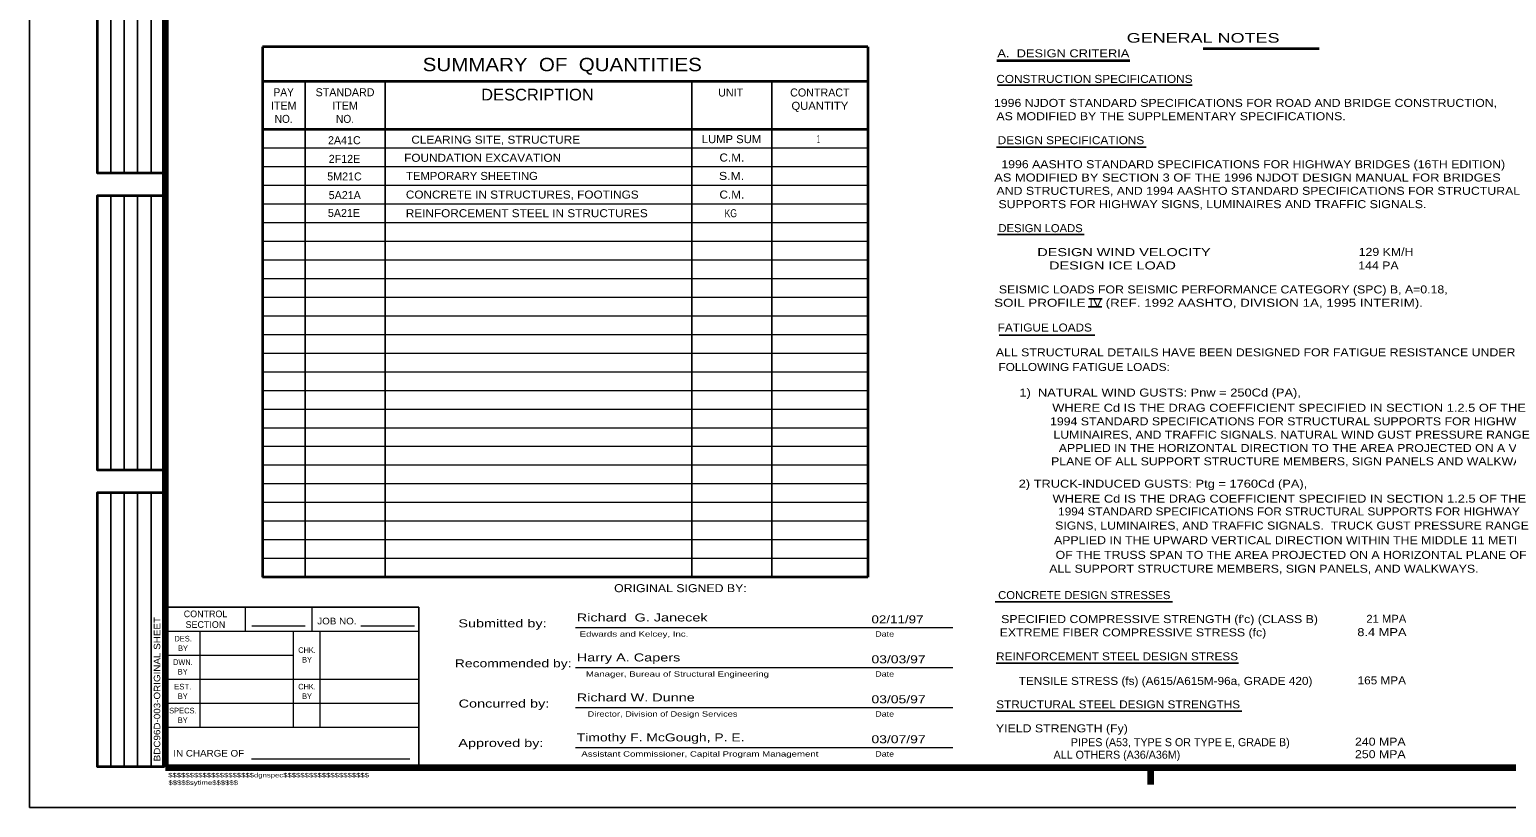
# Model space of a CAD drawing. Extents: x 312601.858 to 312602.699, y 144420.109 to 144420.704.
# Drawn here: x 312601.858 to 312602.412, y 144420.109 to 144420.401 of the extents above; entities that cross this region are included whole.
import ezdxf
from ezdxf.enums import TextEntityAlignment as Align

# ---------------------------------------------------------------- set-up
doc = ezdxf.new("R2010")
doc.units = 0
doc.header["$LTSCALE"] = 0.0012
for name, color, linetype, lineweight in [('1', 7, 'Continuous', 25), ('2', 7, 'Continuous', 13), ('39', 7, 'Continuous', 13), ('60', 7, 'Continuous', 25)]:
    doc.layers.add(name, color=color, linetype=linetype, lineweight=lineweight)
doc.layers.add('4', color=7, linetype='Continuous')

msp = doc.modelspace()

# ---------------------------------------------------------------- linework, layer by layer
at = {"layer": '1', "lineweight": 35}
for p, q in [((312601.9451, 144420.3949), (312601.9451, 144420.1959)), ((312602.1721, 144420.3949), (312601.9451, 144420.3949)), ((312602.1721, 144420.3949), (312602.1721, 144420.1959)), ((312602.1721, 144420.3819), (312601.9451, 144420.3819)), ((312602.1721, 144420.3639), (312601.9451, 144420.3639)), ((312602.1721, 144420.1959), (312601.9451, 144420.1959))]:
    msp.add_line(p, q, dxfattribs=at)
at = {"layer": '1'}
for p, q in [((312601.9611, 144420.3819), (312601.9611, 144420.1959)), ((312601.9911, 144420.3819), (312601.9911, 144420.1959)), ((312602.1061, 144420.3819), (312602.1061, 144420.1959)), ((312602.1361, 144420.3819), (312602.1361, 144420.1959))]:
    msp.add_line(p, q, dxfattribs=at)
at = {"layer": '1', "lineweight": 13}
for p, q in [((312602.1721, 144420.3569), (312601.9451, 144420.3569)), ((312602.1721, 144420.3499), (312601.9451, 144420.3499)), ((312602.1721, 144420.3429), (312601.9451, 144420.3429)), ((312602.1721, 144420.3359), (312601.9451, 144420.3359)), ((312602.1721, 144420.3289), (312601.9451, 144420.3289)), ((312602.1721, 144420.3219), (312601.9451, 144420.3219)), ((312602.1721, 144420.3149), (312601.9451, 144420.3149)), ((312602.1721, 144420.3079), (312601.9451, 144420.3079)), ((312602.1721, 144420.3009), (312601.9451, 144420.3009)), ((312602.1721, 144420.2939), (312601.9451, 144420.2939)), ((312602.1721, 144420.2869), (312601.9451, 144420.2869)), ((312602.1721, 144420.2799), (312601.9451, 144420.2799)), ((312602.1721, 144420.2729), (312601.9451, 144420.2729)), ((312602.1721, 144420.2659), (312601.9451, 144420.2659)), ((312602.1721, 144420.2589), (312601.9451, 144420.2589)), ((312602.1721, 144420.2519), (312601.9451, 144420.2519)), ((312602.1721, 144420.2449), (312601.9451, 144420.2449)), ((312602.1721, 144420.2379), (312601.9451, 144420.2379)), ((312602.1721, 144420.2309), (312601.9451, 144420.2309)), ((312602.1721, 144420.2239), (312601.9451, 144420.2239)), ((312602.1721, 144420.2169), (312601.9451, 144420.2169)), ((312602.1721, 144420.2099), (312601.9451, 144420.2099)), ((312602.1721, 144420.2029), (312601.9451, 144420.2029)), ((312602.1721, 144420.1959), (312601.9451, 144420.1959)), ((312602.0625, 144420.177), (312602.204, 144420.177)), ((312602.0625, 144420.162), (312602.204, 144420.162)), ((312602.0625, 144420.147), (312602.204, 144420.147)), ((312602.0625, 144420.132), (312602.204, 144420.132))]:
    msp.add_line(p, q, dxfattribs=at)
at = {"layer": '2', "lineweight": 35}
for p, q in [((312602.2979, 144420.3943), (312602.3414, 144420.3943)), ((312602.2205, 144420.3898), (312602.2704, 144420.3898))]:
    msp.add_line(p, q, dxfattribs=at)
at = {"layer": '2', "lineweight": 25}
for p, q in [((312602.2207, 144420.3805), (312602.2937, 144420.3805)), ((312602.2204, 144420.3573), (312602.2765, 144420.3573)), ((312602.2208, 144420.3245), (312602.2532, 144420.3245)), ((312602.2548, 144420.2974), (312602.2599, 144420.2974)), ((312602.255, 144420.3004), (312602.26, 144420.3004)), ((312602.2214, 144420.2867), (312602.2573, 144420.2867)), ((312602.2199, 144420.1867), (312602.2864, 144420.1867)), ((312602.2203, 144420.1637), (312602.3111, 144420.1637)), ((312602.2203, 144420.1456), (312602.3124, 144420.1456))]:
    msp.add_line(p, q, dxfattribs=at)
at = {"layer": '39', "lineweight": 25}
for p, q in [((312601.8578, 144420.1095), (312601.8578, 144420.7035)), ((312601.9088, 144420.1847), (312602.0038, 144420.1847)), ((312602.0038, 144420.1247), (312602.0038, 144420.1847)), ((312601.8578, 144420.1095), (312602.6988, 144420.1095))]:
    msp.add_line(p, q, dxfattribs=at)
at = {"layer": '39', "lineweight": 158}
for p, q in [((312601.9088, 144420.1247), (312601.9088, 144420.6645)), ((312601.9088, 144420.1245), (312602.6838, 144420.1245)), ((312602.2783, 144420.1181), (312602.2783, 144420.1245))]:
    msp.add_line(p, q, dxfattribs=at)
at = {"layer": '39'}
for p, q in [((312601.9088, 144420.1247), (312601.9088, 144420.1847)), ((312601.9388, 144420.1757), (312601.9388, 144420.1847)), ((312601.9638, 144420.1757), (312601.9638, 144420.1847)), ((312601.9088, 144420.1757), (312602.0038, 144420.1757)), ((312601.9218, 144420.1397), (312601.9218, 144420.1757)), ((312601.9412, 144420.1777), (312601.9611, 144420.1777)), ((312601.9568, 144420.1397), (312601.9568, 144420.1757)), ((312601.9668, 144420.1397), (312601.9668, 144420.1757)), ((312601.982, 144420.1777), (312602.0022, 144420.1777)), ((312601.9088, 144420.1667), (312601.9568, 144420.1667)), ((312601.9088, 144420.1577), (312602.0038, 144420.1577)), ((312601.9088, 144420.1487), (312602.0038, 144420.1487)), ((312601.9088, 144420.1397), (312602.0038, 144420.1397)), ((312601.9088, 144420.1247), (312602.0038, 144420.1247)), ((312601.941, 144420.1277), (312602.0004, 144420.1277))]:
    msp.add_line(p, q, dxfattribs=at)
at = {"layer": '60'}
for p, q in [((312601.8883, 144420.3475), (312601.8883, 144420.4505)), ((312601.8933, 144420.3475), (312601.8933, 144420.4505)), ((312601.8983, 144420.3475), (312601.8983, 144420.4505)), ((312601.9034, 144420.3475), (312601.9034, 144420.4505)), ((312601.8883, 144420.2361), (312601.8883, 144420.3391)), ((312601.8933, 144420.2361), (312601.8933, 144420.3391)), ((312601.8983, 144420.2361), (312601.8983, 144420.3391)), ((312601.9034, 144420.2361), (312601.9034, 144420.3391)), ((312601.8883, 144420.1247), (312601.8883, 144420.2277)), ((312601.8933, 144420.1247), (312601.8933, 144420.2277)), ((312601.8983, 144420.1247), (312601.8983, 144420.2277)), ((312601.9034, 144420.1247), (312601.9034, 144420.2277))]:
    msp.add_line(p, q, dxfattribs=at)
at = {"layer": '60', "lineweight": 35}
for points in [[(312601.9084, 144420.3475), (312601.8833, 144420.3475), (312601.8833, 144420.4505), (312601.9084, 144420.4505)], [(312601.9084, 144420.2361), (312601.8833, 144420.2361), (312601.8833, 144420.3391), (312601.9084, 144420.3391)], [(312601.9084, 144420.1247), (312601.8833, 144420.1247), (312601.8833, 144420.2277), (312601.9084, 144420.2277)]]:
    msp.add_lwpolyline(points, dxfattribs=at)

# ---------------------------------------------------------------- texts
at = {"layer": '1'}
for s, height, p in [('CONTROL', 0.0025, (312601.9238, 144420.1809)), ('SECTION', 0.0025, (312601.92375, 144420.1769)), ('DES.', 0.0021, (312601.9154, 144420.1718)), ('SPECS.', 0.0021, (312601.9153, 144420.1448))]:
    msp.add_text(s, height=height, dxfattribs=at).set_placement(p, align=Align.CENTER)
for s, height, width, p in [('JOB NO.', 0.0025, 1.1, (312601.97305, 144420.1782)), ('BY', 0.0021, 0.9, (312601.91535, 144420.1682)), ('CHK.', 0.0021, 0.95, (312601.96185, 144420.1675)), ('DWN.', 0.0021, 0.9, (312601.9153, 144420.163)), ('BY', 0.0021, 0.9, (312601.96185, 144420.1639)), ('BY', 0.0021, 0.9, (312601.91525, 144420.1594)), ('EST.', 0.0021, 1.05, (312601.91525, 144420.1538)), ('BY', 0.0021, 0.9, (312601.91525, 144420.1502)), ('CHK.', 0.0021, 0.95, (312601.96185, 144420.1538)), ('BY', 0.0021, 0.9, (312601.96185, 144420.1502)), ('BY', 0.0021, 0.9, (312601.91525, 144420.1412)), ('IN CHARGE OF', 0.0025, 1.1, (312601.925, 144420.1286))]:
    msp.add_text(s, height=height, dxfattribs=dict(at, width=width)).set_placement(p, align=Align.CENTER)
at = {"layer": '2'}
for s, height, width, p in [('                         GENERAL NOTES', 0.0036, 1.4, (312602.27445, 144420.3965)), ('SUMMARY  OF  QUANTITIES', 0.005, 1.15, (312602.05755, 144420.3858)), ('A.  DESIGN CRITERIA', 0.003, 1.2, (312602.24545, 144420.391)), ('PAY', 0.003, 0.95, (312601.9531, 144420.3764)), ('CONSTRUCTION SPECIFICATIONS', 0.003, 1.1, (312602.2571, 144420.3814)), ('DESCRIPTION', 0.0044, 1.05, (312602.04825, 144420.3748)), ('QUANTITY', 0.003, 1.05, (312602.15415, 144420.3713)), ('1996 NJDOT STANDARD SPECIFICATIONS FOR ROAD AND BRIDGE CONSTRUCTION,', 0.003, 1.15, (312602.31375, 144420.3724)), ('NO.', 0.003, 0.95, (312601.9531, 144420.3664)), ('NO.', 0.003, 0.95, (312601.9761, 144420.3664)), ('AS MODIFIED BY THE SUPPLEMENTARY SPECIFICATIONS.', 0.003, 1.15, (312602.28585, 144420.3674)), ('CLEARING SITE, STRUCTURE', 0.003, 1.1, (312602.0326, 144420.3586)), ('LUMP SUM', 0.003, 1.05, (312602.121, 144420.3588)), ('1', 0.003, 0.45, (312602.1536, 144420.3588)), ('DESIGN SPECIFICATIONS', 0.003, 1.1, (312602.2483, 144420.3584)), ('FOUNDATION EXCAVATION', 0.003, 1.1, (312602.0277, 144420.3518)), ('C.M.', 0.003, 1.1, (312602.12115, 144420.3519)), ('1996 AASHTO STANDARD SPECIFICATIONS FOR HIGHWAY BRIDGES (16TH EDITION)', 0.003, 1.15, (312602.31665, 144420.3494)), ('TEMPORARY SHEETING', 0.003, 1.05, (312602.0237, 144420.345)), ('S.M.', 0.003, 1.15, (312602.12105, 144420.345)), ('AS MODIFIED BY SECTION 3 OF THE 1996 NJDOT DESIGN MANUAL FOR BRIDGES', 0.003, 1.2, (312602.3145, 144420.3444)), ('CONCRETE IN STRUCTURES, FOOTINGS', 0.003, 1.1, (312602.04255, 144420.338)), ('C.M.', 0.003, 1.1, (312602.12115, 144420.338)), ('AND STRUCTURES, AND 1994 AASHTO STANDARD SPECIFICATIONS FOR STRUCTURAL', 0.003, 1.15, (312602.31855, 144420.3394)), ('SUPPORTS FOR HIGHWAY SIGNS, LUMINAIRES AND TRAFFIC SIGNALS.', 0.003, 1.15, (312602.30135, 144420.3344)), ('REINFORCEMENT STEEL IN STRUCTURES', 0.003, 1.1, (312602.04425, 144420.331)), ('KG', 0.003, 0.8, (312602.12075, 144420.331)), ('DESIGN LOADS', 0.003, 1.05, (312602.2369, 144420.3254)), ('DESIGN WIND VELOCITY                              ', 0.003, 1.35, (312602.29075, 144420.3164)), ('129 KM/H', 0.003, 1.15, (312602.36645, 144420.3165)), ('DESIGN ICE LOAD                                   ', 0.003, 1.35, (312602.2902, 144420.3114)), ('144 PA', 0.003, 1.15, (312602.3636, 144420.3114)), ('SEISMIC LOADS FOR SEISMIC PERFORMANCE CATEGORY (SPC) B, A=0.18, ', 0.003, 1.15, (312602.30605, 144420.3024)), ('SOIL PROFILE IV (REF. 1992 AASHTO, DIVISION 1A, 1995 INTERIM).', 0.003, 1.25, (312602.2999, 144420.2974)), ('FATIGUE LOADS', 0.003, 1.1, (312602.2385, 144420.2881)), ('ALL STRUCTURAL DETAILS HAVE BEEN DESIGNED FOR FATIGUE RESISTANCE UNDER THE', 0.003, 1.15, (312602.3228, 144420.2788)), ('FOLLOWING FATIGUE LOADS:', 0.003, 1.1, (312602.25325, 144420.2733)), ('1)  NATURAL WIND GUSTS: Pnw = 250Cd (PA),', 0.003, 1.2, (312602.28175, 144420.2637)), ('WHERE Cd IS THE DRAG COEFFICIENT SPECIFIED IN SECTION 1.2.5 OF THE', 0.003, 1.2, (312602.3301, 144420.258)), ('1994 STANDARD SPECIFICATIONS FOR STRUCTURAL SUPPORTS FOR HIGHWAY SIGNS,', 0.003, 1.15, (312602.3394, 144420.2529)), ('LUMINAIRES, AND TRAFFIC SIGNALS. NATURAL WIND GUST PRESSURE RANGE', 0.003, 1.15, (312602.33105, 144420.2479)), ('PLANE OF ALL SUPPORT STRUCTURE MEMBERS, SIGN PANELS AND WALKWAYS.', 0.003, 1.15, (312602.33275, 144420.2379)), ('APPLIED IN THE HORIZONTAL DIRECTION TO THE AREA PROJECTED ON A VERTICAL', 0.003, 1.15, (312602.33935, 144420.2429)), ('2) TRUCK-INDUCED GUSTS: Ptg = 1760Cd (PA),', 0.003, 1.2, (312602.2828, 144420.2295)), ('WHERE Cd IS THE DRAG COEFFICIENT SPECIFIED IN SECTION 1.2.5 OF THE', 0.003, 1.2, (312602.3302, 144420.2239)), ('1994 STANDARD SPECIFICATIONS FOR STRUCTURAL SUPPORTS FOR HIGHWAY', 0.003, 1.1, (312602.33005, 144420.2191)), ('SIGNS, LUMINAIRES, AND TRAFFIC SIGNALS.  TRUCK GUST PRESSURE RANGE', 0.003, 1.15, (312602.3312, 144420.2138)), ('APPLIED IN THE UPWARD VERTICAL DIRECTION WITHIN THE MIDDLE 11 METERS', 0.003, 1.15, (312602.33295, 144420.2083)), ('OF THE TRUSS SPAN TO THE AREA PROJECTED ON A HORIZONTAL PLANE OF', 0.003, 1.15, (312602.33085, 144420.2028)), ('ALL SUPPORT STRUCTURE MEMBERS, SIGN PANELS, AND WALKWAYS.', 0.003, 1.15, (312602.32065, 144420.1976)), ('CONCRETE DESIGN STRESSES', 0.003, 1.05, (312602.2533, 144420.1877)), ('Submitted by:', 0.003, 1.35, (312602.03515, 144420.1771)), ("SPECIFIED COMPRESSIVE STRENGTH (f'c) (CLASS B)             ", 0.003, 1.15, (312602.28985, 144420.1787)), ('21 MPA', 0.003, 1.05, (312602.36655, 144420.1788)), ('Edwards and Kelcey, Inc.', 0.002, 1.35, (312602.08445, 144420.1736)), ('Date', 0.002, 1.25, (312602.17845, 144420.1736)), ('EXTREME FIBER COMPRESSIVE STRESS (fc)            ', 0.003, 1.15, (312602.27925, 144420.1737)), ('8.4 MPA', 0.003, 1.2, (312602.3649, 144420.1738)), ('Recommended by:', 0.003, 1.3, (312602.03915, 144420.1621)), ('REINFORCEMENT STEEL DESIGN STRESS', 0.003, 1.1, (312602.2656, 144420.1647)), ('Manager, Bureau of Structural Engineering', 0.002, 1.35, (312602.10075, 144420.1586)), ('Date', 0.002, 1.25, (312602.17845, 144420.1586)), ('TENSILE STRESS (fs) (A615/A615M-96a, GRADE 420)                         ', 0.003, 1.1, (312602.2991, 144420.1555)), ('165 MPA', 0.003, 1.1, (312602.36485, 144420.1557)), ('Concurred by:', 0.003, 1.35, (312602.0357, 144420.147)), ('STRUCTURAL STEEL DESIGN STRENGTHS', 0.003, 1.1, (312602.266, 144420.1467)), ('Director, Division of Design Services', 0.002, 1.3, (312602.09515, 144420.1436)), ('Date', 0.002, 1.25, (312602.17845, 144420.1436)), ('YIELD STRENGTH (Fy)', 0.003, 1.15, (312602.2449, 144420.1377)), ('240 MPA', 0.003, 1.15, (312602.3643, 144420.1327)), ('Approved by:', 0.003, 1.35, (312602.03455, 144420.1322)), ('Assistant Commissioner, Capital Program Management', 0.002, 1.35, (312602.10915, 144420.1286)), ('Date', 0.002, 1.25, (312602.17845, 144420.1286)), ('250 MPA', 0.003, 1.15, (312602.3643, 144420.128))]:
    msp.add_text(s, height=height, dxfattribs=dict(at, width=width)).set_placement(p, align=Align.CENTER)
for s, p in [('STANDARD', (312601.9761, 144420.3764)), ('ITEM', (312601.9531, 144420.3714)), ('ITEM', (312601.9761, 144420.3714)), ('UNIT', (312602.1207, 144420.3763)), ('CONTRACT', (312602.15415, 144420.3763)), ('2A41C', (312601.97585, 144420.3584)), ('2F12E', (312601.9759, 144420.3514)), ('5M21C', (312601.9759, 144420.3448)), ('5A21A', (312601.976, 144420.3378)), ('5A21E', (312601.9757, 144420.3311)), ('     ALL OTHERS (A36/A36M)                                   ', (312602.28225, 144420.1278)), ('     PIPES (A53, TYPE S OR TYPE E, GRADE B)                                        ', (312602.3088, 144420.1325))]:
    msp.add_text(s, height=0.003, dxfattribs=at).set_placement(p, align=Align.CENTER)
at = {"layer": '2', "width": 1.15}
msp.add_text('BDC96D-003-ORIGINAL SHEET', height=0.0024, rotation=90, dxfattribs=at).set_placement((312601.9068, 144420.1539), align=Align.CENTER)
at = {"layer": '2', "width": 1.3}
for s, p in [('$$$$$$$$$$$$$$$$$$$$dgnspec$$$$$$$$$$$$$$$$$$$$', (312601.9098, 144420.1208)), ('$$$$$sytime$$$$$$', (312601.9099, 144420.118))]:
    msp.add_text(s, height=0.001664, dxfattribs=at).set_placement(p)
at = {"layer": '4'}
for s, width, p in [('ORIGINAL SIGNED BY:', 1.15, (312602.077, 144420.1903)), ('Richard  G. Janecek', 1.35, (312602.063, 144420.1793)), ('02/11/97', 1.25, (312602.1735, 144420.1786)), ('Harry A. Capers', 1.35, (312602.063, 144420.1643)), ('03/03/97', 1.3, (312602.1735, 144420.1636)), ('Richard W. Dunne', 1.35, (312602.063, 144420.1493)), ('03/05/97', 1.3, (312602.1735, 144420.1486)), ('Timothy F. McGough, P. E.', 1.3, (312602.063, 144420.1343)), ('03/07/97', 1.3, (312602.1735, 144420.1336))]:
    msp.add_text(s, height=0.003, dxfattribs=dict(at, width=width)).set_placement(p)

doc.saveas('drawing.dxf')
